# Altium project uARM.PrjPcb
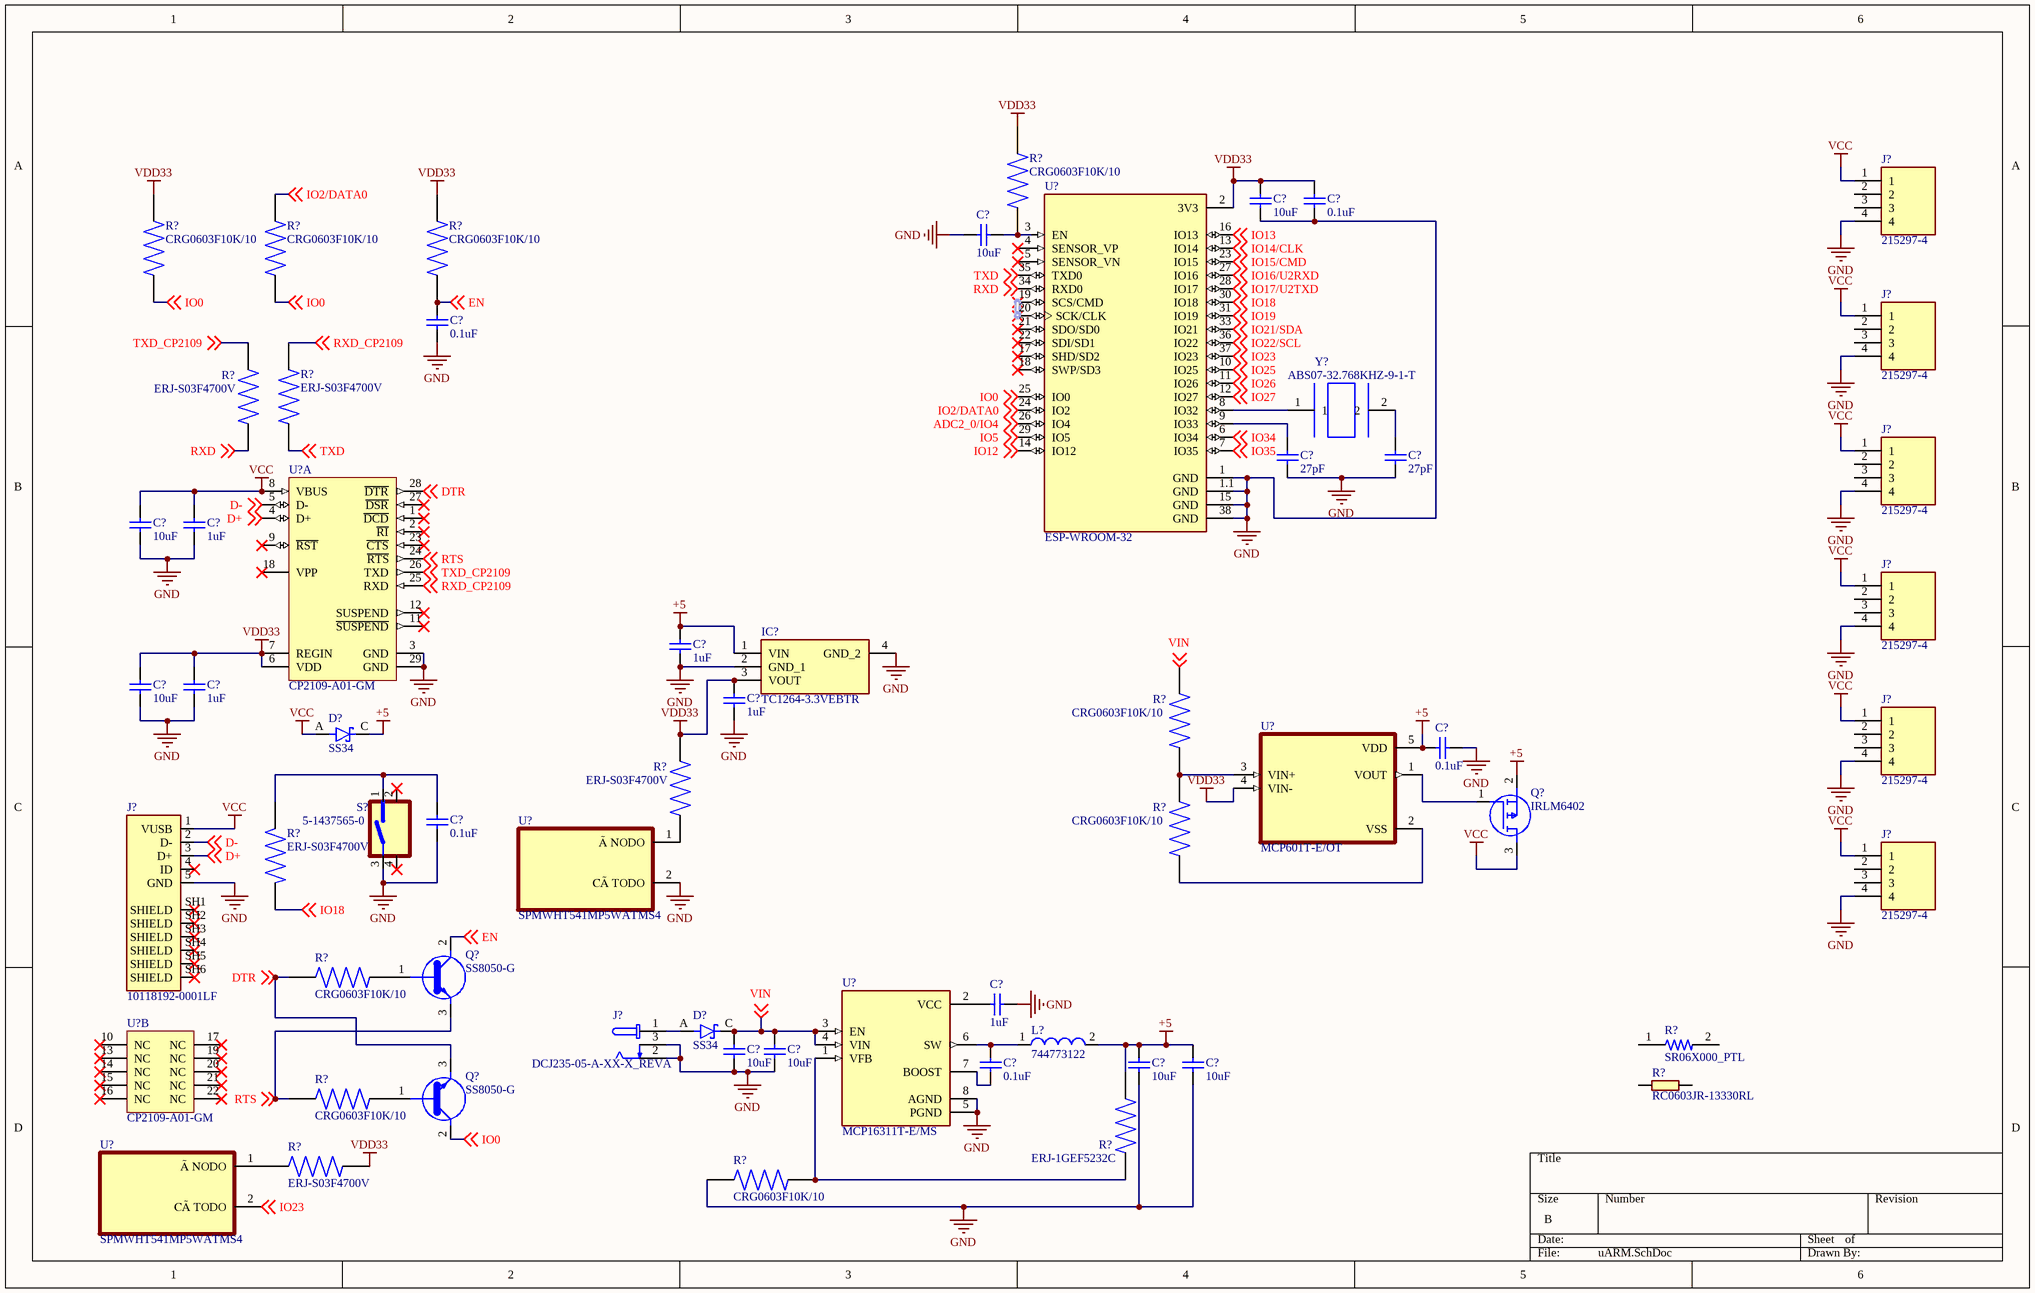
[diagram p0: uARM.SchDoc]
1 sheet, 61 parts. Net scope: global (net labels, ports and power ports of the same name join across sheets).
Board file: PCB1.PcbDoc

## Sheet uARM.SchDoc
size B

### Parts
(Parts that share a designator on the sheet are numbered #1, #2 ... from top to bottom, then left to right.)
C?#1  value 10uF  [C_3216[1206]_N]  (hidden comment: C1206C106K3RACTU)
C?#2  value 0.1uF  [C_3216[1206]_N]  (hidden comment: C1206C106K3RACTU)
C?#3  value 10uF  [C_3216[1206]_N]  (hidden comment: C1206C106K3RACTU)
C?#4  value 0.1uF  [C_3216[1206]_N]  (hidden comment: C1206C106K3RACTU)
C?#5  value 27pF  [C_3216[1206]_N]  (hidden comment: C1206C106K3RACTU)
C?#6  value 27pF  [C_3216[1206]_N]  (hidden comment: C1206C106K3RACTU)
C?#7  value 10uF  [C_3216[1206]_N]  (hidden comment: C1206C106K3RACTU)
C?#8  value 1uF  [C_3216[1206]_N]  (hidden comment: C1206C106K3RACTU)
C?#9  value 1uF  [C_3216[1206]_N]  (hidden comment: C1206C106K3RACTU)
C?#10  value 1uF  [C_3216[1206]_N]  (hidden comment: C1206C106K3RACTU)
C?#11  value 10uF  [C_3216[1206]_N]  (hidden comment: C1206C106K3RACTU)
C?#12  value 1uF  [C_3216[1206]_N]  (hidden comment: C1206C106K3RACTU)
C?#13  value 0.1uF  [C_3216[1206]_N]  (hidden comment: C1206C106K3RACTU)
C?#14  value 0.1uF  [C_3216[1206]_N]  (hidden comment: C1206C106K3RACTU)
C?#15  value 1uF  [C_3216[1206]_N]  (hidden comment: C1206C106K3RACTU)
C?#16  value 10uF  [C_3216[1206]_N]  (hidden comment: C1206C106K3RACTU)
C?#17  value 10uF  [C_3216[1206]_N]  (hidden comment: C1206C106K3RACTU)
C?#18  value 0.1uF  [C_3216[1206]_N]  (hidden comment: C1206C106K3RACTU)
C?#19  value 10uF  [C_3216[1206]_N]  (hidden comment: C1206C106K3RACTU)
C?#20  value 10uF  [C_3216[1206]_N]  (hidden comment: C1206C106K3RACTU)
D?#1  SS34  [DIOM7959X265N]
D?#2  SS34  [DIOM7959X265N]
IC?  TC1264-3.3VEBTR  [TC126433VEBTR]
J?#1  215297-4  [TE_215297-4]
J?#2  215297-4  [TE_215297-4]
J?#3  215297-4  [TE_215297-4]
J?#4  215297-4  [TE_215297-4]
J?#5  215297-4  [TE_215297-4]
J?#6  10118192-0001LF  [AMPHENOL_10118192-0001LF]
J?#7  215297-4  [TE_215297-4]
J?#8  DCJ235-05-A-XX-X_REVA  [GCT_DCJ235-05-A-XX-X_REVA]
L?  744773122  [WE-PD2-S]
Q?#1  IRLM6402  [SOT95P237X112-3N]
Q?#2  SS8050-G  [MBTB-T-SOT23]
Q?#3  SS8050-G  [MBTB-T-SOT23]
R?#1  CRG0603F10K/10  [RESC1608X55N]
R?#2  CRG0603F10K/10  [RESC1608X55N]
R?#3  CRG0603F10K/10  [RESC1608X55N]
R?#4  CRG0603F10K/10  [RESC1608X55N]
R?#5  ERJ-S03F4700V  [RESC1608X55N]
R?#6  ERJ-S03F4700V  [RESC1608X55N]
R?#7  CRG0603F10K/10  [RESC1608X55N]
R?#8  ERJ-S03F4700V  [RESC1608X55N]
R?#9  CRG0603F10K/10  [RESC1608X55N]
R?#10  ERJ-S03F4700V  [RESC1608X55N]
R?#11  CRG0603F10K/10  [RESC1608X55N]
R?#12  SR06X000_PTL  [RESC1608X55]
R?#13  RC0603JR-13330RL  [0603]
R?#14  CRG0603F10K/10  [RESC1608X55N]
R?#15  ERJ-1GEF5232C  [RESC0603X26N]
R?#16  ERJ-S03F4700V  [RESC1608X55N]
R?#17  CRG0603F10K/10  [RESC1608X55N]
S?  5-1437565-0  [SW_5-1437565-0]
U?#1  ESP-WROOM-32  [MODULE_ESP-WROOM-32]
U?#2  CP2109-A01-GM  [SLAB-QFN-28-3125x3125TP_L]  (part A of 2)
U?#3  MCP601T-E/OT  [SOT95P270X145-5N]
U?#4  SPMWHT541MP5WATMS4  [LED_SPMWHT541MP5WAPKS4]
U?#5  CP2109-A01-GM  [SLAB-QFN-28-3125x3125TP_L]  (part B of 2)
U?#6  MCP16311T-E/MS  [SOP65P490X110-8N]
U?#7  SPMWHT541MP5WATMS4  [LED_SPMWHT541MP5WAPKS4]
Y?  ABS07-32.768KHZ-9-1-T  [XTAL320X150X90]

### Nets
+5: C?#9.1 C?#13.2 C?#19.2 C?#20.2 D?#1.C(K) IC?.1(VIN) L?.2 Q?#1.2(S) R?#15.2 U?#3.5(VDD)
GND: C?#1.1 C?#2.1 C?#3.2 C?#4.1 C?#5.1 C?#6.1 C?#7.1 C?#8.1 C?#9.2 C?#10.2 C?#11.1 C?#12.1 C?#13.1 C?#14.1 C?#15.1 C?#16.1 C?#17.1 C?#19.1 C?#20.1 IC?.2(GND_1) IC?.4(GND_2) J?#1.4 J?#2.4 J?#3.4 J?#4.4 J?#5.4 J?#6.5(GND) J?#7.4 J?#8.2 J?#8.3 R?#17.1 S?.3 U?#1.1(GND) U?#1.1.1(GND) U?#1.15(GND) U?#1.38(GND) U?#2.3(GND) U?#2.29(GND) U?#4.2(CÃTODO) U?#6.5(PGND) U?#6.8(AGND)
VCC: C?#7.2 C?#8.2 D?#1.A J?#1.1 J?#2.1 J?#3.1 J?#4.1 J?#5.1 J?#6.1(VUSB) J?#7.1 Q?#1.3(D) U?#2.8(VBUS)
VDD33: C?#1.2 C?#2.2 C?#10.1 C?#11.2 C?#12.2 IC?.3(VOUT) R?#1.2 R?#2.1 R?#4.1 R?#8.2 R?#16.1 U?#1.2(3V3) U?#2.6(VDD) U?#2.7(REGIN) U?#3.4(VIN-)
ADC2_0/IO4: U?#1.26(IO4) ; off-sheet ADC2_0/IO4
D+: J?#6.3(D+) U?#2.4(D+) ; off-sheet D+
D-: J?#6.2(D-) U?#2.5(D-) ; off-sheet D-
DTR: Q?#3.3(C) R?#11.2 U?#2.28(~{DTR}) ; off-sheet DTR
EN: C?#4.2 Q?#2.2(E) R?#4.2 ; off-sheet EN
IO0: Q?#3.2(E) R?#2.2 R?#3.2 U?#1.25(IO0) ; off-sheet IO0
IO2/DATA0: R?#3.1 U?#1.24(IO2) ; off-sheet IO2/DATA0
IO5: U?#1.29(IO5) ; off-sheet IO5
IO12: U?#1.14(IO12) ; off-sheet IO12
IO13: U?#1.16(IO13) ; off-sheet IO13
IO14/CLK: U?#1.13(IO14) ; off-sheet IO14/CLK
IO15/CMD: U?#1.23(IO15) ; off-sheet IO15/CMD
IO16/U2RXD: U?#1.27(IO16) ; off-sheet IO16/U2RXD
IO17/U2TXD: U?#1.28(IO17) ; off-sheet IO17/U2TXD
IO18: R?#10.2 U?#1.30(IO18) ; off-sheet IO18
IO19: U?#1.31(IO19) ; off-sheet IO19
IO21/SDA: U?#1.33(IO21) ; off-sheet IO21/SDA
IO22/SCL: U?#1.36(IO22) ; off-sheet IO22/SCL
IO23: U?#1.37(IO23) U?#7.2(CÃTODO) ; off-sheet IO23
IO25: U?#1.10(IO25) ; off-sheet IO25
IO26: U?#1.11(IO26) ; off-sheet IO26
IO27: U?#1.12(IO27) ; off-sheet IO27
IO34: U?#1.6(IO34) ; off-sheet IO34
IO35: U?#1.7(IO35) ; off-sheet IO35
RTS: Q?#2.3(C) R?#14.2 U?#2.24(~{RTS}) ; off-sheet RTS
RXD: R?#5.1 U?#1.34(RXD0) ; off-sheet RXD
RXD_CP2109: R?#6.2 U?#2.25(RXD) ; off-sheet RXD_CP2109
TXD: R?#6.1 U?#1.35(TXD0) ; off-sheet TXD
TXD_CP2109: R?#5.2 U?#2.26(TXD) ; off-sheet TXD_CP2109
VIN: C?#16.2 C?#17.2 D?#2.C(K) R?#7.1 U?#6.3(EN) U?#6.4(VIN) ; off-sheet VIN
NetC?#3_1: C?#3.1 R?#1.1 U?#1.3(EN)
NetC?#5_2: C?#5.2 U?#1.9(IO33)
NetC?#6_2: C?#6.2 Y?.2
NetC?#14_2: C?#14.2 R?#10.1 S?.1
NetC?#15_2: C?#15.2 U?#6.2(VCC)
NetC?#18_1: C?#18.1 U?#6.7(BOOST)
NetC?#18_2: C?#18.2 L?.1 U?#6.6(SW)
NetD?#2_A: D?#2.A J?#8.1
NetQ?#1_1: Q?#1.1(G) U?#3.1(VOUT)
NetQ?#2_1: Q?#2.1(B) R?#11.1
NetQ?#3_1: Q?#3.1(B) R?#14.1
NetR?#7_2: R?#7.2 R?#9.1 U?#3.3(VIN+)
NetR?#8_1: R?#8.1 U?#4.1(ÃNODO)
NetR?#9_2: R?#9.2 U?#3.2(VSS)
NetR?#15_1: R?#15.1 R?#17.2 U?#6.1(VFB)
NetR?#16_2: R?#16.2 U?#7.1(ÃNODO)
NetU?#1_8: U?#1.8(IO32) Y?.1

Not connected (* = marked no-connect by the designer): J?#1 2 3; J?#2 2 3; J?#3 2 3; J?#4 2 3; J?#5 2 3; J?#6 4(ID)* SH1(SHIELD)* SH2(SHIELD)* SH3(SHIELD)* SH4(SHIELD)* SH5(SHIELD)* SH6(SHIELD)*; J?#7 2 3; R?#12 1 2; R?#13 1 2; S? 2* 4(1)*; U?#1 4(SENSOR_VP)* 5(SENSOR_VN)* 17(SHD/SD2)* 18(SWP/SD3)* 19(SCS/CMD)* 20(SCK/CLK)* 21(SDO/SD0)* 22(SDI/SD1)*; U?#2 1(~{DCD})* 2(~{RI})* 9(~{RST})* 11(~{SUSPEND})* 12(SUSPEND)* 18(VPP)* 23(~{CTS})* 27(~{DSR})*; U?#5 10(NC)* 13(NC)* 14(NC)* 15(NC)* 16(NC)* 17(NC)* 19(NC)* 20(NC)* 21(NC)* 22(NC)*

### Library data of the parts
C?#1-C?#20 = C_10uf_3216[1206]: Capacitor Céramique 10uf XR7 25V 10%; Manufacturer: KEMET
D?#1 D?#2 = SS34: Diode Schottky 40V 3A 2-Pin SMC T/R; MF: {'manufacturer': u'ON Semiconductor'}
IC? = TC1264-3.3VEBTR: Integrated Circuit; Manufacturer_Name: Microchip
J?#1-J?#5 J?#7 = 215297-4: MF: {'manufacturer': u'TE Connectivity'}
J?#6 = 10118192-0001LF: Single Port 5 Contact Horizontal Right Angle Shielded Micro B USB 2.0 Connector; MF: {'manufacturer': u'FCI'}
J?#8 = DCJ235-05-A-XX-X_REVA: DC Power Jack, Thru-Hole, Horizontal, with Locating Pegs, D2.35mm; MF: {'manufacturer': u'Global Connector Technology'}
L? = 744773122: SMD Power Inductor WE-PD2, L = 22.0 µH; Inductance: 22.0 ÂµH
Q?#1 = IRLM6402: MOSFET (P-Channel); Manufacturer_Name: Infineon
Q?#2 Q?#3 = SS8050-G: <b>Bipolar Transistors - BJT NPN TRANSISTOR 1.5A 40V</b><p> Source: <a href="https://componentsearchengine.com/Datasheets/1/SS8050-G.pdf"> Datasheet </a>; MF: {'manufacturer': u'Comchip Technology'}
R?#1-R?#4 R?#7 R?#9 R?#11 R?#14 R?#17 = CRG0603F10K/10: Thick Film Resistors - SMD CRG0603 1% 10K 10K RL; MF: {'manufacturer': u'TE Connectivity'}
R?#5 R?#6 R?#8 R?#10 R?#16 = ERJ-S03F4700V: MF: {'manufacturer': u'Panasonic'}
R?#12 = SR06X000_PTL: MP: SR06X000 PTL; MF: {'manufacturer': u'Walsin Technologies'}
R?#13 = RC0603JR-13330RL: https://octopart.com/rc0603fr-13100kl-yageo-12819546; MF: {'manufacturer': u'Yageo'}
R?#15 = ERJ-1GEF5232C: Res Thick Film 0201 52.3K Ohm 1% 0.05W(1/20W) Â±200ppm/C SMD T/R; MF: {'manufacturer': u'Panasonic'}
S? = 5-1437565-0: Switch Tactile OFF (ON) Round Button Gull Wing 0.05A 12VDC 1.57N SMD T/R; MF: {'manufacturer': u'TE Connectivity'}
U?#1 = ESP-WROOM-32: Module: combo; GPIO, I2C x2, I2S x2, SDIO, SPI x3, UART x3; 19.5dBm; MF: {'manufacturer': u'Espressif Systems'}
U?#2 U?#5 = CP2109-A01-GM: Single-Chip USB to UART Bridge, 1024 Bytes EEPROM, -40 to 85 degC, 28-pin QFN, Tube; Manufacturer: Silicon Labs; Sub-Family: USB Bridges; Internal Oscillator: TRUE
U?#3 = MCP601T-E/OT: MF: {'manufacturer': u'Microchip'}
U?#4 U?#7 = SPMWHT541MP5WATMS4: MF: {'manufacturer': u'Samsung Semiconductor,'}
U?#6 = MCP16311T-E/MS: The MCP16311/2 is a compact, high-efficiency, fixed frequency, synchronous step-down DC-DC converter in an 8-pin MSOP, or 2 x 3 TDFN package that operates from input voltage sources up to 30V. Integrated features include a high-side and a low-side switch, fixed frequency peak current mode control, internal compensation, peak current limit and overtemperature protection. The MCP16311/2 provides all the active functions for local DC-DC conversion, with fast transient response and accurate regulation.; MF: {'manufacturer': u'Microchip Technology'}
Y? = ABS07-32.768KHZ-9-1-T: ABS07 Series 32.768 kHz Â±20 ppm 12.5 pF -40 to +85 C SMT Low Profile Crystal; MF: {'manufacturer': u'Abracon'}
